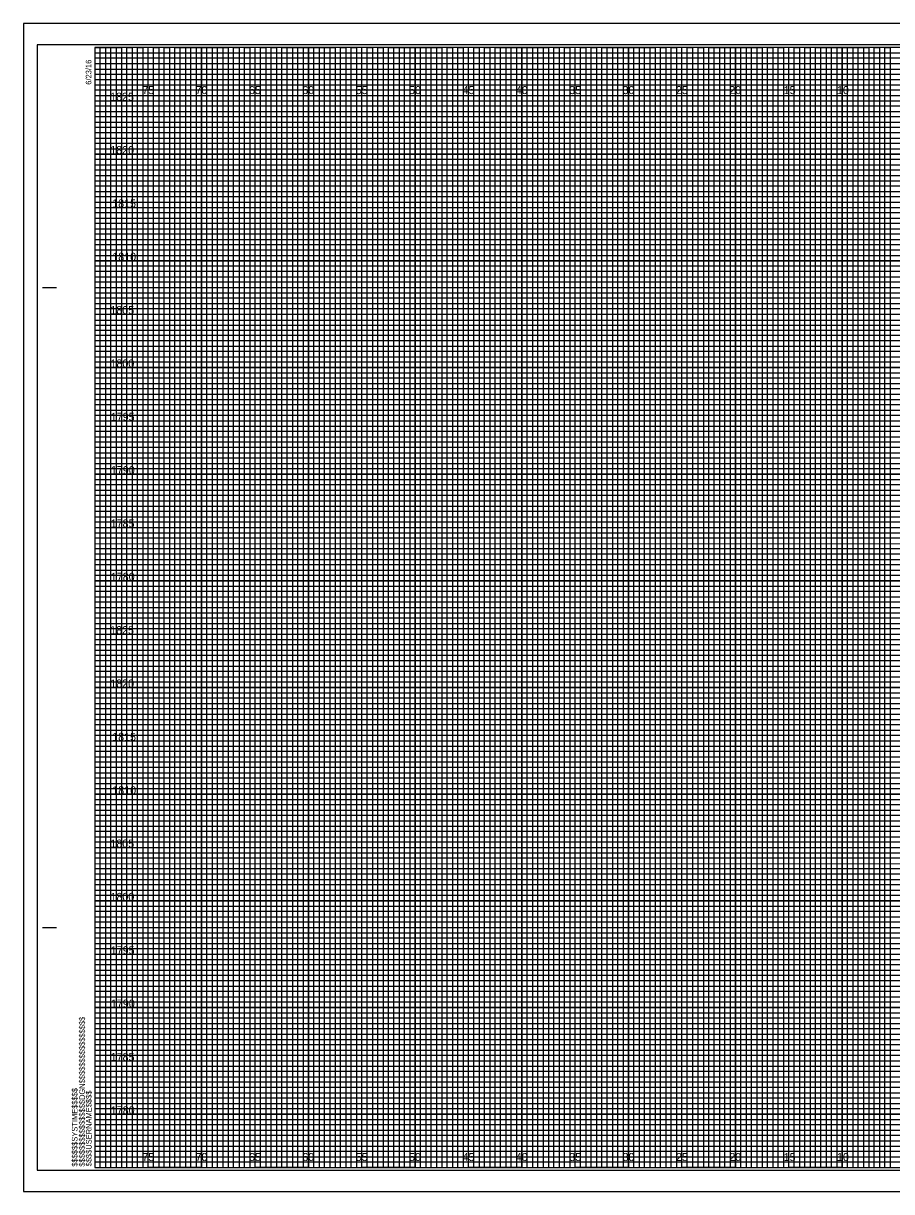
# Model space of a CAD drawing. Extents: x -7 to 162, y -2 to 767.
# Drawn here: x -6.7 to 74.6, y 107.7 to 217.2 of the extents above; entities that cross this region are included whole.
import ezdxf

# ---------------------------------------------------------------- set-up
doc = ezdxf.new("R2010")
doc.units = 0
for name, color, linetype in [('Prop Grid Mask', 7, 'Continuous'), ('Prop XS Elevation Labels', 7, 'Continuous'), ('Sheet Cross Section CELL', 7, 'Continuous'), ('Sheet Cross Section Grid Major CELL', 7, 'Continuous'), ('Sheet Cross Section Grid Middle CELL', 7, 'Continuous'), ('Sheet Cross Section Grid Minor 1 CELL', 7, 'Continuous'), ('Sheet Cross Section Grid Minor 2 CELL', 7, 'Continuous'), ('Sheet Cutting Line CELL', 7, 'Continuous'), ('Sheet DOT Grid CELL', 7, 'Continuous'), ('Sheet Plot Border Inside CELL', 7, 'Continuous'), ('Sheet Plot Border Outside CELL', 7, 'Continuous')]:
    doc.layers.add(name, color=color, linetype=linetype)

msp = doc.modelspace()

# ---------------------------------------------------------------- linework, layer by layer
at = {"layer": 'Sheet Cross Section CELL'}
for p, q in [((-4.9, 192.5), (-3.65, 192.5)), ((-4.85, 192.5), (-3.6, 192.5)), ((-4.9, 132.5), (-3.65, 132.5)), ((-4.85, 132.5), (-3.6, 132.5)), ((0, 110), (0, 110)), ((0, 110), (0, 110)), ((0, 110), (0, 110)), ((0, 110), (0, 110)), ((0, 110), (0, 110)), ((0, 110), (0, 110)), ((0, 110), (0, 110))]:
    msp.add_line(p, q, dxfattribs=at)
msp.add_lwpolyline([(160, 215), (0, 215), (0, 110), (160, 110)], close=True, dxfattribs=at)
at = {"layer": 'Sheet Cross Section Grid Major CELL'}
for p, q in [((5, 215), (0, 215)), ((5, 110), (5, 215)), ((15, 215), (10, 215)), ((10, 215), (10, 110)), ((15, 110), (15, 215)), ((25, 215), (20, 215)), ((20, 215), (20, 110)), ((25, 110), (25, 215)), ((35, 215), (30, 215)), ((30, 215), (30, 110)), ((35, 110), (35, 215)), ((45, 215), (40, 215)), ((40, 215), (40, 110)), ((45, 110), (45, 215)), ((55, 215), (50, 215)), ((50, 215), (50, 110)), ((55, 110), (55, 215)), ((65, 215), (60, 215)), ((60, 215), (60, 110)), ((65, 110), (65, 215)), ((75, 215), (70, 215)), ((70, 215), (70, 110)), ((10, 110), (5, 110)), ((20, 110), (15, 110)), ((30, 110), (25, 110)), ((40, 110), (35, 110)), ((50, 110), (45, 110)), ((60, 110), (55, 110)), ((70, 110), (65, 110))]:
    msp.add_line(p, q, dxfattribs=at)
for points in [[(0, 210), (160, 210), (160, 205), (0, 205)], [(0, 200), (160, 200), (160, 195), (0, 195)], [(0, 190), (160, 190), (160, 185), (0, 185)], [(0, 180), (160, 180), (160, 175), (0, 175)], [(0, 170), (160, 170), (160, 165), (0, 165)], [(0, 160), (160, 160), (160, 155), (0, 155)], [(0, 150), (160, 150), (160, 145), (0, 145)], [(0, 140), (160, 140), (160, 135), (0, 135)], [(0, 130), (160, 130), (160, 125), (0, 125)], [(0, 120), (160, 120), (160, 115), (0, 115)]]:
    msp.add_lwpolyline(points, dxfattribs=at)
at = {"layer": 'Sheet Cross Section Grid Middle CELL'}
for points in [[(0, 215), (2.5, 215), (2.5, 110), (7.5, 110), (7.5, 215), (12.5, 215), (12.5, 110), (17.5, 110), (17.5, 215), (22.5, 215), (22.5, 110), (27.5, 110), (27.5, 215), (32.5, 215), (32.5, 110), (37.5, 110), (37.5, 215), (42.5, 215), (42.5, 110), (47.5, 110), (47.5, 215), (52.5, 215), (52.5, 110), (57.5, 110), (57.5, 215), (62.5, 215), (62.5, 110), (67.5, 110), (67.5, 215), (72.5, 215), (72.5, 110), (77.5, 110)], [(0, 212.5), (137.5, 212.5)], [(0, 202.5), (160, 202.5), (160, 207.5), (0, 207.5)], [(0, 192.5), (160, 192.5), (160, 197.5), (0, 197.5)], [(0, 182.5), (160, 182.5), (160, 187.5), (0, 187.5)], [(0, 172.5), (160, 172.5), (160, 177.5), (0, 177.5)], [(0, 162.5), (160, 162.5), (160, 167.5), (0, 167.5)], [(0, 152.5), (160, 152.5), (160, 157.5), (0, 157.5)], [(0, 142.5), (160, 142.5), (160, 147.5), (0, 147.5)], [(0, 132.5), (160, 132.5), (160, 137.5), (0, 137.5)], [(0, 122.5), (160, 122.5), (160, 127.5), (0, 127.5)], [(0, 112.5), (160, 112.5), (160, 117.5), (0, 117.5)]]:
    msp.add_lwpolyline(points, dxfattribs=at)
at = {"layer": 'Sheet Cross Section Grid Minor 1 CELL'}
for p, q in [((0, 214.5), (130, 214.5)), ((130, 213.99), (0, 213.99)), ((0, 213.99), (0, 213.5)), ((0, 213.5), (130, 213.5)), ((130, 212.94), (0, 212.94)), ((0, 212.94), (0, 212)), ((0, 212), (160, 212))]:
    msp.add_line(p, q, dxfattribs=at)
for points in [[(0, 211.5), (135, 211.5), (160, 211.5), (160, 211), (0, 211)], [(0, 210.5), (160, 210.5), (160, 209.5), (0, 209.5)], [(0, 209), (160, 209), (160, 208.5), (0, 208.49)], [(0, 208), (160, 208), (160, 207), (0, 207)], [(0, 206.5), (160, 206.5), (160, 206), (0, 206)], [(0, 205.5), (160, 205.5), (160, 204.5), (0, 204.5)], [(0, 204), (160, 204), (160, 203.5), (0, 203.5)], [(0, 203), (160, 203), (160, 202), (0, 202)], [(0, 201.5), (160, 201.5), (160, 201), (0, 201)], [(0, 200.5), (160, 200.5), (160, 199.5), (0, 199.5)], [(0, 199), (160, 199), (160, 198.5), (0, 198.5)], [(0, 198), (160, 198), (160, 196.97), (160, 196.5), (160, 196), (0, 196)], [(0, 197), (160, 197), (160, 196.5), (0, 196.5)], [(0, 195.5), (160, 195.5), (160, 194.5), (0, 194.52)], [(0, 194.52), (160, 194.5), (160, 194), (0, 194)], [(0, 193.5), (160, 193.5), (160, 193), (0, 193)], [(0, 192), (160, 192), (160, 191.5), (0, 191.5)], [(0, 191), (160, 191), (160, 190.5), (0, 190.5)], [(-0.04, 189.44), (160, 189.44), (160, 188.94), (-0.04, 188.94)], [(0, 188.5), (160, 188.5), (160, 188), (0, 188)], [(0, 187), (160, 187), (160, 186.5), (0, 186.5)], [(0, 186), (160, 186), (160, 185.5), (0, 185.5)], [(0, 184.5), (160, 184.5), (160, 184), (0, 184)], [(0, 183.5), (160, 183.5), (160, 183), (0, 183)], [(0, 182), (160, 182), (160, 181.5), (0, 181.5)], [(0, 181), (160, 181), (160, 180.5), (0, 180.5)], [(0, 179.5), (160, 179.5), (160, 178.99), (0, 179)], [(0, 178.5), (160, 178.5), (160, 178), (0, 178)], [(0, 177), (160, 177), (160, 176.5), (0, 176.5)], [(0, 176), (160, 176), (160, 175.5), (0, 175.5)], [(0, 174.5), (160, 174.5), (160, 174), (0, 174)], [(0, 173.5), (160, 173.5), (160, 173), (0, 173)], [(0, 172), (160, 172), (160, 171.5), (0, 171.5)], [(0, 171), (160, 171), (160, 170.5), (0, 170.5)], [(0, 169.5), (160, 169.5), (160, 169), (0, 169)], [(0, 168.5), (160.03, 168.46), (160, 168), (0, 168)], [(0, 167), (160, 167), (160, 166.5), (0, 166.5)], [(0, 166), (160, 166), (160, 165.5), (0, 165.5)], [(0, 164.5), (160, 164.5), (160, 164), (0, 164)], [(0, 163.5), (160, 163.5), (160, 163), (0, 163)], [(0, 162), (160, 162), (160, 161.5), (0, 161.5)], [(0, 161), (160, 161), (160, 160.5), (0, 160.5)], [(0, 159.5), (160, 159.5), (160, 159), (0, 159)], [(0, 158.5), (160, 158.5), (160, 158), (0, 158)], [(0, 157), (160, 157), (160, 156.5), (0, 156.5)], [(0, 156), (160, 156), (160, 155.5), (0, 155.5)], [(0, 154.5), (160, 154.5), (160, 154), (0, 154)], [(0, 153.5), (160, 153.5), (160, 153), (0, 153)], [(0, 152), (160, 152), (160, 151.5), (0, 151.5)], [(0, 151), (160, 151), (160, 150.5), (0, 150.5)], [(0, 149.5), (160, 149.5), (160, 148.99), (0, 149)], [(0, 148.5), (160, 148.5), (160, 148), (0, 148)], [(0, 147), (160, 147), (160, 146.5), (0, 146.5)], [(0, 146), (160, 146), (160, 145.5), (0, 145.5)], [(0, 144.5), (160, 144.5), (160, 144), (0, 144)], [(0, 143.5), (160, 143.5), (160, 143), (0, 143)], [(0, 142), (160, 142), (160, 141.5), (0, 141.5)], [(0, 141), (160, 141), (160, 140.5), (0, 140.5)], [(0, 139.5), (160, 139.5), (160, 139), (0, 139)], [(0, 138.5), (160.03, 138.46), (160, 138), (0, 138)], [(0, 137), (160, 137), (160, 136.5), (0, 136.5)], [(0, 136), (160, 136), (160, 135.5), (0, 135.5)], [(0, 134.5), (160, 134.5), (160, 134), (0, 134)], [(0, 133.5), (160, 133.5), (160, 133), (0, 133)], [(0, 132), (160, 132), (160, 131.5), (0, 131.5)], [(0, 131), (160, 131), (160, 130.5), (0, 130.5)], [(0, 129.5), (160, 129.5), (160, 129), (0, 129)], [(0, 128.5), (160, 128.5), (160, 128), (0, 128)], [(0, 127), (160, 127), (160, 126.5), (0, 126.5)], [(0, 126), (160, 126), (160, 125.5), (0, 125.5)], [(0, 124.5), (160, 124.5), (160, 124), (0, 124)], [(0, 123.5), (160, 123.5), (160, 123), (0, 123)], [(0, 122), (160, 122), (160, 121.5), (0, 121.5)], [(0, 121), (160, 121), (160, 120.5), (0, 120.5)], [(0, 119.5), (160, 119.5), (160, 119), (0, 119)], [(0, 118.5), (160, 118.5), (160, 118), (0, 118)], [(0, 117), (160, 117), (160, 116.5), (0, 116.5)], [(0, 116), (160, 116), (160, 115.5), (0, 115.5)], [(0, 114.5), (160, 114.5), (160, 114), (0, 114)], [(0, 113.5), (160, 113.5), (160, 113), (0, 113)], [(0, 112), (160, 112), (160, 111.5), (0, 111.5)], [(0, 111), (160, 111), (160, 110.5), (0, 110.5)]]:
    msp.add_lwpolyline(points, dxfattribs=at)
at = {"layer": 'Sheet Cross Section Grid Minor 2 CELL'}
for points in [[(0, 110), (0.5, 110), (0.5, 215), (1, 215), (1, 110)], [(1, 110), (1.5, 110), (1.5, 215), (2, 215), (2, 110)], [(2.5, 110), (3, 110), (3, 215), (3.5, 215), (3.5, 110)], [(3.5, 110), (4, 110), (4, 215), (4.5, 215), (4.5, 110)], [(5, 110), (5.5, 110), (5.5, 215), (6, 215), (6, 110)], [(6, 110), (6.5, 110), (6.5, 215), (7, 215), (7, 110)], [(7.5, 110), (8, 110), (8, 215), (8.5, 215), (8.5, 110)], [(8.5, 110), (9, 110), (9, 215), (9.5, 215), (9.5, 110)], [(10, 110), (10.5, 110), (10.5, 215), (11, 215), (11, 110)], [(11, 110), (11.5, 110), (11.5, 215), (12, 215), (12, 110)], [(12.5, 110), (13, 110), (13, 215), (13.5, 215), (13.5, 110)], [(13.5, 110), (14, 110), (14, 215), (14.5, 215), (14.5, 110)], [(15, 110), (15.5, 110), (15.5, 215), (16, 215), (16, 110)], [(16, 110), (16.5, 110), (16.5, 215), (17, 215), (17, 110)], [(17.5, 110), (18, 110), (18, 215), (18.5, 215), (18.5, 110)], [(18.5, 110), (19, 110), (19, 215), (19.5, 215), (19.5, 110)], [(20, 110), (20.5, 110), (20.5, 215), (21, 215), (21, 110)], [(21, 110), (21.5, 110), (21.5, 215), (22, 215), (22, 110)], [(22.5, 110), (23, 110), (23, 215), (23.5, 215), (23.5, 110)], [(23.5, 110), (24, 110), (24, 215), (24.5, 215), (24.5, 110)], [(25, 110), (25.5, 110), (25.5, 215), (26, 215), (26, 110)], [(26, 110), (26.5, 110), (26.5, 215), (27, 215), (27, 110)], [(27.5, 110), (28, 110), (28, 215), (28.5, 215), (28.5, 110)], [(28.5, 110), (29, 110), (29, 215), (29.5, 215), (29.5, 110)], [(30, 110), (30.5, 110), (30.5, 215), (31, 215), (31, 110)], [(31, 110), (31.5, 110), (31.5, 215), (32, 215), (32, 110)], [(32.5, 110), (33, 110), (33, 215), (33.5, 215), (33.5, 110)], [(33.5, 110), (34, 110), (34, 215), (34.5, 215), (34.5, 110)], [(35, 110), (35.5, 110), (35.5, 215), (36, 215), (36, 110)], [(36, 110), (36.5, 110), (36.5, 215), (37, 215), (37, 110)], [(37.5, 110), (38, 110), (38, 215), (38.5, 215), (38.5, 110)], [(38.5, 110), (39, 110), (39, 215), (39.5, 215), (39.5, 110)], [(40, 110), (40.5, 110), (40.5, 215), (41, 215), (41, 110)], [(41, 110), (41.5, 110), (41.5, 215), (42, 215), (42, 110)], [(42.5, 110), (43, 110), (43, 215), (43.5, 215), (43.5, 110)], [(43.5, 110), (44, 110), (44, 215), (44.5, 215), (44.5, 110)], [(45, 110), (45.5, 110), (45.5, 215), (46, 215), (46, 110)], [(46, 110), (46.5, 110), (46.5, 215), (47, 215), (47, 110)], [(47.5, 110), (48, 110), (48, 215), (48.5, 215), (48.5, 110)], [(48.5, 110), (49, 110), (49, 215), (49.5, 215), (49.5, 110)], [(50, 110), (50.5, 110), (50.5, 215), (51, 215), (51, 110)], [(51, 110), (51.5, 110), (51.5, 215), (52, 215), (52, 110)], [(52.5, 110), (53, 110), (53, 215), (53.5, 215), (53.5, 110)], [(53.5, 110), (54, 110), (54, 215), (54.5, 215), (54.5, 110)], [(55, 110), (55.5, 110), (55.5, 215), (56, 215), (56, 110)], [(56, 110), (56.5, 110), (56.5, 215), (57, 215), (57, 110)], [(57.5, 110), (58, 110), (58, 215), (58.5, 215), (58.5, 110)], [(58.5, 110), (59, 110), (59, 215), (59.5, 215), (59.5, 110)], [(60, 110), (60.5, 110), (60.5, 215), (61, 215), (61, 110)], [(61, 110), (61.5, 110), (61.5, 215), (62, 215), (62, 110)], [(62.5, 110), (63, 110), (63, 215), (63.5, 215), (63.5, 110)], [(63.5, 110), (64, 110), (64, 215), (64.5, 215), (64.5, 110)], [(65, 110), (65.5, 110), (65.5, 215), (66, 215), (66, 110)], [(66, 110), (66.5, 110), (66.5, 215), (67, 215), (67, 110)], [(67.5, 110), (68, 110), (68, 215), (68.5, 215), (68.5, 110)], [(68.5, 110), (69, 110), (69, 215), (69.5, 215), (69.5, 110)], [(70, 110), (70.5, 110), (70.5, 215), (71, 215), (71, 110)], [(71, 110), (71.5, 110), (71.5, 215), (72, 215), (72, 110)], [(72.5, 110), (73, 110), (73, 215), (73.5, 215), (73.5, 110)], [(73.5, 110), (74, 110), (74, 215), (74.5, 215), (74.5, 110)]]:
    msp.add_lwpolyline(points, dxfattribs=at)
at = {"layer": 'Sheet Cutting Line CELL'}
for p, q in [((161.65, 217.25), (-6.7, 217.25)), ((-6.7, 217.25), (-6.7, 107.75)), ((-6.7, 107.75), (161.65, 107.75))]:
    msp.add_line(p, q, dxfattribs=at)
at = {"layer": 'Sheet DOT Grid CELL'}
for p, q in [((5, 110), (5, 215)), ((10, 110), (10, 215)), ((15, 110), (15, 215)), ((20, 110), (20, 215)), ((25, 110), (25, 215)), ((30, 110), (30, 215)), ((35, 110), (35, 215)), ((40, 110), (40, 215)), ((45, 110), (45, 215)), ((50, 110), (50, 215)), ((55, 110), (55, 215)), ((60, 110), (60, 215)), ((65, 110), (65, 215)), ((70, 110), (70, 215)), ((0, 210), (160, 210)), ((0, 205), (160, 205)), ((0, 200), (160, 200)), ((0, 195), (160, 195)), ((0, 190), (160, 190)), ((0, 185), (160, 185)), ((0, 180), (160, 180)), ((0, 175), (160, 175)), ((0, 170), (160, 170)), ((0, 165), (160, 165)), ((0, 160), (160, 160)), ((0, 155), (160, 155)), ((0, 150), (160, 150)), ((0, 145), (160, 145)), ((0, 140), (160, 140)), ((0, 135), (160, 135)), ((0, 130), (160, 130)), ((0, 125), (160, 125)), ((0, 120), (160, 120)), ((0, 115), (160, 115))]:
    msp.add_line(p, q, dxfattribs=at)
at = {"layer": 'Sheet Plot Border Inside CELL'}
msp.add_lwpolyline([(-5.4, 109.75), (161.2, 109.75), (161.2, 215.25), (-5.4, 215.25)], close=True, dxfattribs=at)
at = {"layer": 'Sheet Plot Border Outside CELL'}
msp.add_lwpolyline([(-6.7, 107.75), (161.65, 107.75), (161.65, 217.25), (-6.7, 217.25)], close=True, dxfattribs=at)

# ---------------------------------------------------------------- texts
at = {"layer": 'Prop Grid Mask'}
for s, p in [('75', (4.44, 210.62)), ('70', (9.43, 210.62)), ('65', (14.44, 210.62)), ('60', (19.43, 210.62)), ('55', (24.44, 210.62)), ('50', (29.43, 210.62)), ('45', (34.44, 210.62)), ('40', (39.43, 210.62)), ('35', (44.44, 210.62)), ('30', (49.43, 210.62)), ('25', (54.44, 210.62)), ('20', (59.43, 210.62)), ('15', (64.53, 210.62)), ('10', (69.52, 210.62)), ('75', (4.44, 110.62)), ('70', (9.43, 110.62)), ('65', (14.44, 110.62)), ('60', (19.43, 110.62)), ('55', (24.44, 110.62)), ('50', (29.43, 110.62)), ('45', (34.44, 110.62)), ('40', (39.43, 110.62)), ('35', (44.44, 110.62)), ('30', (49.43, 110.62)), ('25', (54.44, 110.62)), ('20', (59.43, 110.62)), ('15', (64.53, 110.62)), ('10', (69.52, 110.62))]:
    msp.add_text(s, height=0.75, dxfattribs=at).set_placement(p)
at = {"layer": 'Prop XS Elevation Labels'}
for s, p in [('1825', (1.43, 210)), ('1820', (1.44, 205)), ('1815', (1.62, 200)), ('1810', (1.63, 195)), ('1805', (1.45, 190)), ('1800', (1.46, 185)), ('1795', (1.49, 180)), ('1790', (1.5, 175)), ('1785', (1.48, 170)), ('1780', (1.49, 165)), ('1825', (1.43, 160)), ('1820', (1.44, 155)), ('1815', (1.62, 150)), ('1810', (1.63, 145)), ('1805', (1.45, 140)), ('1800', (1.46, 135)), ('1795', (1.49, 130)), ('1790', (1.5, 125)), ('1785', (1.48, 120)), ('1780', (1.49, 115))]:
    msp.add_text(s, height=0.75, dxfattribs=at).set_placement(p)
at = {"layer": 'Sheet Cross Section CELL'}
for s, p in [('6/23/16', (-0.33, 211.5)), ('$$$$$$$$$$$$$$$$DGN$$$$$$$$$$$$$$$$', (-0.94, 110.09)), ('$$$$$$SYSTIME$$$$$', (-1.63, 110.09)), ('$$$$USERNAME$$$$', (-0.31, 110.12))]:
    msp.add_text(s, height=0.525, rotation=90, dxfattribs=at).set_placement(p)

doc.saveas('drawing.dxf')
